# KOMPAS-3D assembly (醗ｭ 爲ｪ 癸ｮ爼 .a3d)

Referenced files in C:\Users\Артём\Documents\: Фонарик жучок корпус редуктора 2.m3d, Фонарик жучок крышка редуктора левая.m3d, Фонарик жучок крышка редуктора правая.m3d, Фонарик жучок.m3d, Фонарик жучок ручка.m3d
